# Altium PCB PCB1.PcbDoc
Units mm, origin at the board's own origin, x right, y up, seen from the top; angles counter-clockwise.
Board outline 99 x 59.87 mm, 2 copper layers (Top Layer, Bottom Layer); 24 components, 21 nets, 124 pads, 0 vias.
Unrouted connection lines stored in the file: 1.
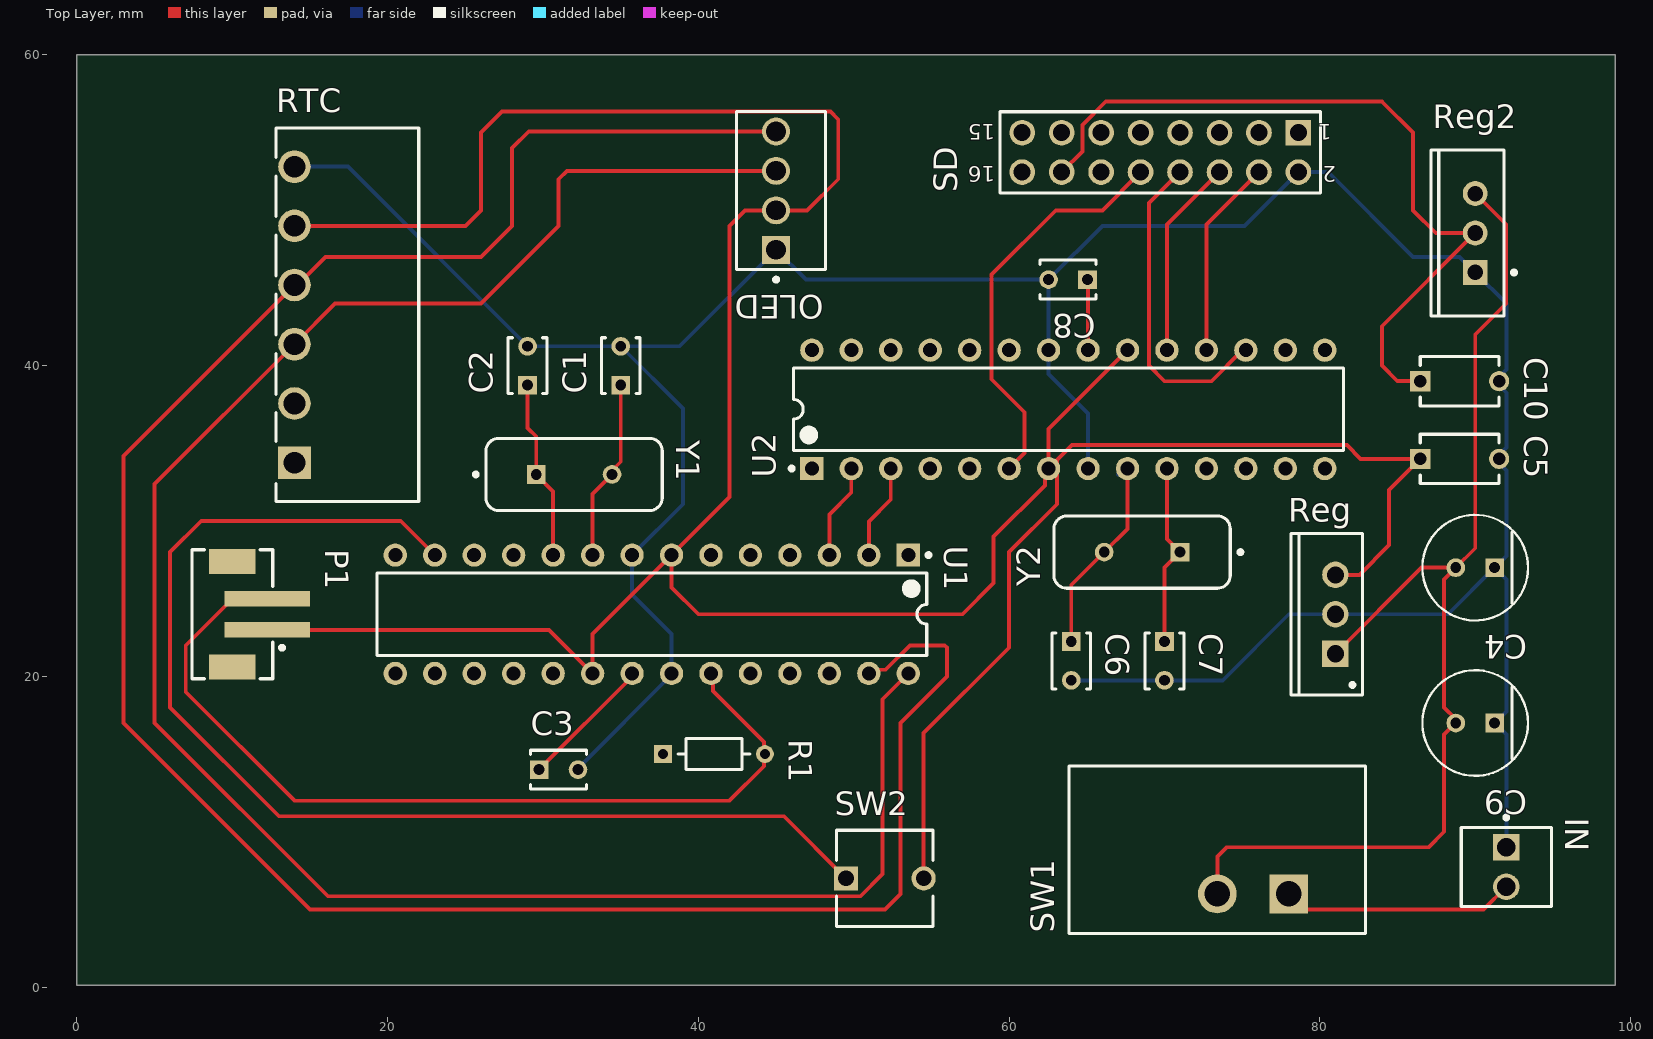
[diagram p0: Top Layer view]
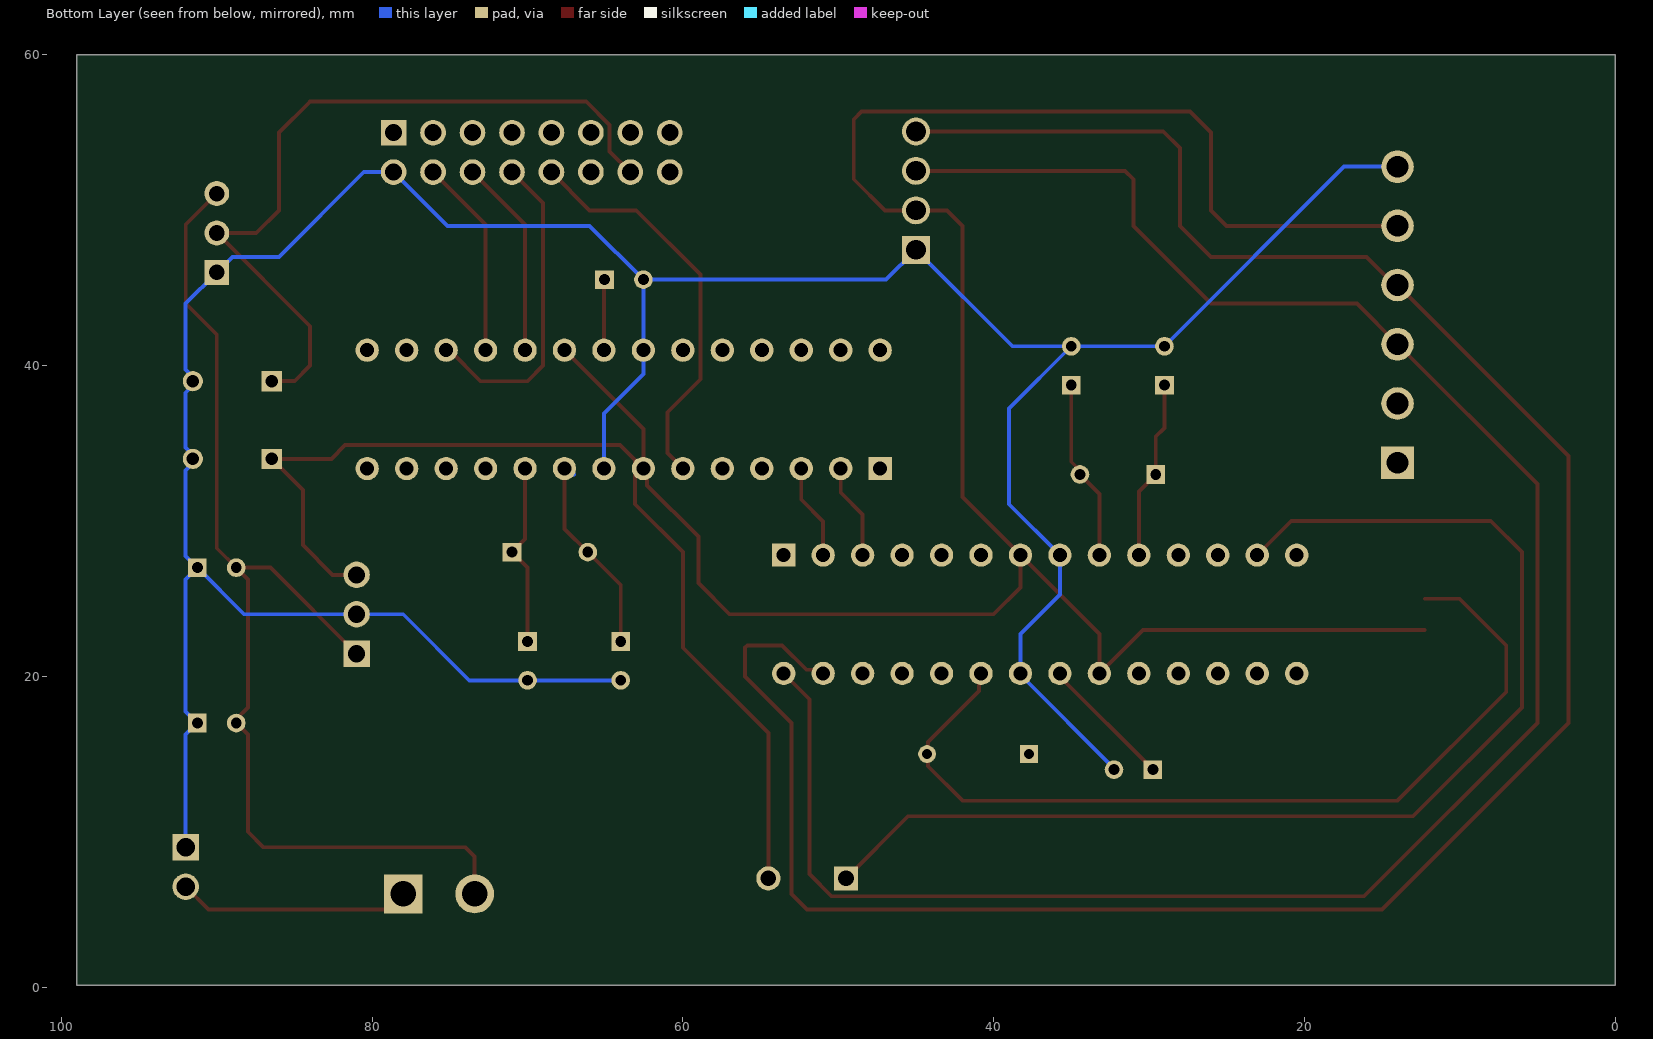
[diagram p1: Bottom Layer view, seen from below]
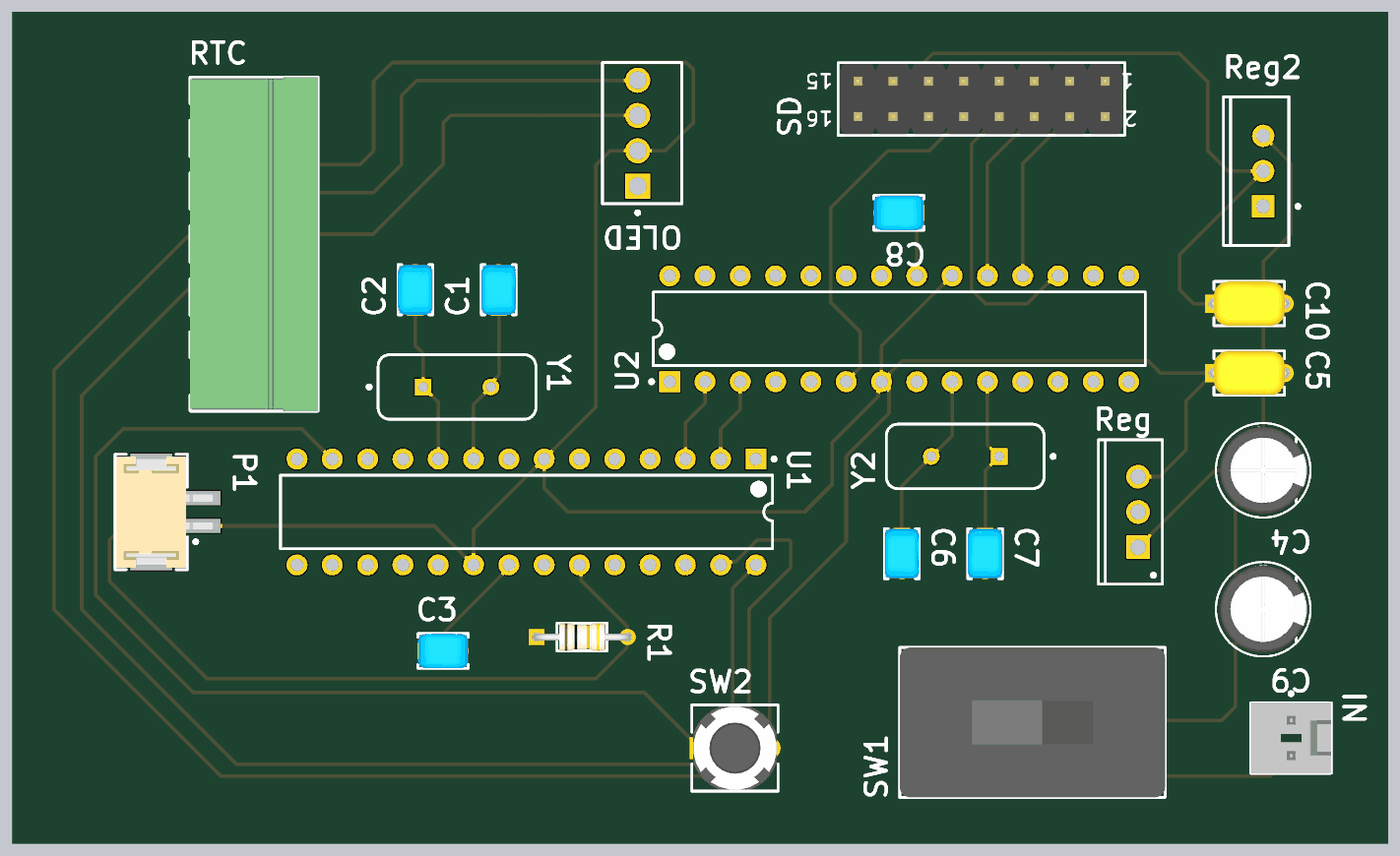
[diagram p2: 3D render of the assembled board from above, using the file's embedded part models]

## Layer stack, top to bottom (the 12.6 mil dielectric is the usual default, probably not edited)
Top Solder: solder mask 0.0102, Solder Resist, Dk 3.5
Top Layer: signal copper 0.0356
Dielectric 1: dielectric 0.32, FR-4, Dk 4.8
Bottom Layer: signal copper 0.0356
Bottom Solder: solder mask 0.0102, Solder Resist, Dk 3.5

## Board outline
0,0.127 99,0.127 99,60 0,60

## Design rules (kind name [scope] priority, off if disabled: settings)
Clearance [All] p1: gap=0.25 ignorepadtopadclearanceinfootprint=FALSE
PolygonConnect [All] p1: connectstyle=Relief reliefconductorwidth=0.254 reliefentries=4 polygonreliefangle="90 Angle" airgapwidth=0.254
RoutingVias [All] p1: holewidth=0.4 width=0.5 viastyle="Through Hole" minholewidth=0.4 minwidth=0.5 maxholewidth=0.8 maxwidth=1
SolderMaskExpansion [All] p1: expansion=0.102 istentingtop=FALSE
Width power [(InNet('3.3V') OR InNet('5V') OR InNet('GND'))] p1: maxlimit=0.3 minlimit=0.2 preferedwidth=0.254
Width [All] p2: maxlimit=0.3 minlimit=0.1 preferedwidth=0.25
30 further rules are at their usual default settings.

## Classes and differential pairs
component class Sheet1: C1 C2 C3 C4 C5 C6 C7 C8 C9 C10 IN OLED P1 R1 Reg Reg2 SD SW1 SW2 U1 Y2

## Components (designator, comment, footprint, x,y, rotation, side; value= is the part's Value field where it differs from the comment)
C1 "22pF" FP-RCE0DB-MFG 35,40 r90 top
C2 "22pF" FP-RCE0DB-MFG 29,40 r90 top
C3 "100nF" FP-RCE0DB-MFG 31,14 r0 top
C4 "4.7uF" FP-RAD-TH-D_6_3_0_5-L_11-MFG 90,27 r180 top
C5 "100nF" FP-C322C104K5R5TA-MFG 89,34 r0 top
C6 "22pF" FP-RCE0DB-MFG 64,21 r270 top
C7 "22pF" FP-RCE0DB-MFG 70,21 r270 top
C8 "100nF" FP-RCE0DB-MFG 63.79,45.54 r180 top
C9 "10uF" FP-RAD-TH-D_6_3_0_5-L_11-MFG 90,17 r180 top
C10 "22uF" FP-C322C104K5R5TA-MFG 89,39 r0 top
IN "9V" MOLX-22-27-2021_V 92,7.73 r270 top
OLED "6" TECO-640456-4 45,51.27 r270 top
P1 "probe" 620302124022 10,24 r270 top
R1 "10k" FP-CF18-MFG 41,15 r0 top value=10kΩ
Reg "5V" TO220 81,24 r90 top
Reg2 "3.3V" NDE0003A 90,48.54 r90 top
RTC "691322310006" 691322310006 17.4,43.285 r90 top
SD "61301621121" 61301621121 69.73,53.73 r180 top
SW1 "on/off" FP-L101011MS02Q-MFG 73.4,8.85 r90 top
SW2 "push button" FP-EVQ11Y04K-MFG 52,7 r0 top
U1 "ATmega328P-PU" 28P3 37,24 r270 top
U2 "ATmega328P-PU" 28P3 63.81,37.19 r90 top
Y1 "16MHz" FOX-FOXSLF160-20 32,33 r0 top
Y2 "16MHz" FOX-FOXSLF160-20 68.56,28 r180 top

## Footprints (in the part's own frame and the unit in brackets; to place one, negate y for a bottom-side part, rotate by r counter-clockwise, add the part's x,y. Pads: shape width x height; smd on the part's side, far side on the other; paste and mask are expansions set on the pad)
28P3 [mm] "28-Pin Plastic Dual In-Line Package (PDIP)"
  rect 1.5x1.5 hole 0.9: 1(-3.81,16.51)
  round 1.5 hole 0.9: 2(-3.81,13.97) 3(-3.81,11.43) 4(-3.81,8.89) 5(-3.81,6.35) 6(-3.81,3.81) 7(-3.81,1.27) 8(-3.81,-1.27) 9(-3.81,-3.81) 10(-3.81,-6.35) 11(-3.81,-8.89) 12(-3.81,-11.43) 13(-3.81,-13.97) 14(-3.81,-16.51) 15(3.81,-16.51) 16(3.81,-13.97) 17(3.81,-11.43) 18(3.81,-8.89) 19(3.81,-6.35) 20(3.81,-3.81) 21(3.81,-1.27) 22(3.81,1.27) 23(3.81,3.81) 24(3.81,6.35) 25(3.81,8.89) 26(3.81,11.43) 27(3.81,13.97) 28(3.81,16.51)
  silkscreen extent -3.93,-17.7 2.65,17.94, body extent -3.6,-17.65 3.6,17.65, height 4.58
61301621121 [mm] "Pin Header, pitch 2.54 mm, THT, Vertical, dual row, 16p"
  rect 1.65x1.65 hole 1.1: 1(-8.89,-1.27)
  round 1.65 hole 1.1: 2(-8.89,1.27) 3(-6.35,-1.27) 4(-6.35,1.27) 5(-3.81,-1.27) 6(-3.81,1.27) 7(-1.27,-1.27) 8(-1.27,1.27) 9(1.27,-1.27) 10(1.27,1.27) 11(3.81,-1.27) 12(3.81,1.27) 13(6.35,-1.27) 14(6.35,1.27) 15(8.89,-1.27) 16(8.89,1.27)
  silkscreen extent -10.31,-2.62 10.31,2.62, body extent -10.16,-2.54 10.16,2.54, height 8.59
620302124022 [mm] "2.00mm SMT Male Vertical Shrouded Header, 2p"
  rect 1x5.5 smd: 1(1,2.25) 2(-1,2.25)
  rect 1.6x3 smd: MP1(-3.4,0) MP2(3.4,0)
  silkscreen extent -4.15,-2.6 4.15,3.32, body extent -4,-2.5 4,4.51, height 6.77
691322310006 [mm] "Horizontal PCB Header, pitch 3.81mm, 06p"
  rect 2.1x2.1 hole 1.4: 1(-9.525,3.4)
  round 2.1 hole 1.4: 2(-5.715,3.4) 3(-1.905,3.4) 4(1.905,3.4) 5(5.715,3.4) 6(9.525,3.4)
  silkscreen extent -12.02,-4.6 12.03,4.6, body extent -12.02,-4.6 12.02,4.6, height 7.25
FOX-FOXSLF160-20 [mm] "THD, 2-Leads, Body 11.35x4.65mm"
  rect 1.2x1.2 hole 0.7: 1(-2.44,0)
  round 1.2 hole 0.7: 2(2.44,0)
  silkscreen extent -6.45,-2.32 5.68,2.32, body extent -5.67,-2.32 5.68,2.33, height 3.6
FP-C322C104K5R5TA-MFG [mm]
  rect 1.3x1.3 hole 0.8 paste-1000 mask+0: 1(-2.54,0)
  round 1.3 hole 0.8 paste-1000 mask+0: 2(2.54,0)
  silkscreen extent -2.54,-1.59 2.54,1.59, body extent -3.29,-1.69 3.29,1.69, height 0.25
FP-CF18-MFG [mm]
  rect 1.15x1.15 hole 0.65 paste-1000 mask+0: 1(-3.28,0)
  round 1.15 hole 0.65 paste-1000 mask+0: 2(3.28,0)
  silkscreen extent -2.3,-1 2.3,1, body extent -3.96,-1.1 3.96,1.1, height 0.25
FP-EVQ11Y04K-MFG [mm]
  rect 1.55x1.55 hole 1 paste-1000 mask+0: A(-2.5,0)
  round 1.55 hole 1 paste-1000 mask+0: B(2.5,0)
  silkscreen extent -3.1,-3.1 3.1,3.1, body extent -3.37,-3.2 3.37,3.2, height 0.25
FP-L101011MS02Q-MFG [mm]
  rect 2.5x2.5 hole 1.65 paste-1000 mask+0: 1(-2.85,-4.6)
  round 2.5 hole 1.65 paste-1000 mask+0: 2(-2.85,0)
  silkscreen extent -5.4,-9.55 5.4,9.55, body extent -5.5,-9.65 5.5,9.65, height 0.25
FP-RAD-TH-D_6_3_0_5-L_11-MFG [mm]
  rect 1.2x1.2 hole 0.7 paste-1000 mask+0: 1(-1.25,0)
  round 1.2 hole 0.7 paste-1000 mask+0: 2(1.25,0)
  silkscreen extent -3.4,-3.4 3.4,3.4, body extent -3.5,-3.5 3.5,3.5, height 0.25
FP-RCE0DB-MFG [mm]
  rect 1.2x1.2 hole 0.7 paste-1000 mask+0: 1(-1.25,0)
  round 1.2 hole 0.7 paste-1000 mask+0: 2(1.25,0)
  silkscreen extent -1.8,-1.25 1.8,1.25, body extent -1.95,-1.35 1.95,1.35, height 0.25
MOLX-22-27-2021_V [mm] "Header, 2-Leads, Body 5.8x5.08mm"
  rect 1.7x1.7 hole 1.19: 1(-1.27,0)
  round 1.7 hole 1.19: 2(1.27,0)
  silkscreen extent -3.31,-2.9 2.54,2.9, body extent -2.54,-2.9 2.54,2.9, height 11.72
NDE0003A [mm] "FM, 3-Leads, Body 10.7x4.7mm, Pitch 2.54mm"
  rect 1.6x1.6 hole 1: 1(-2.54,0)
  round 1.6 hole 1: 2(0,0) 3(2.54,0)
  silkscreen extent -5.35,-2.63 5.35,2.85, body extent -5.4,-1.9 5.4,2.9, height 19.4
TECO-640456-4 [mm] "Through Hole, 4-Leads, Body 10.16x5.72mm, Pitch 2.54mm"
  rect 1.8x1.8 hole 1.27 paste+0: 1(3.81,0)
  round 1.8 hole 1.27 paste+0: 2(1.27,0) 3(-1.27,0) 4(-3.81,0)
  silkscreen extent -5.08,-2.54 5.86,3.18, body extent -5.08,-2.54 5.08,3.18, height 10.03
TO220 [mm] "TO, Thru-Hole, Vertical, Heatsink Mounted; 3 In-Line Leads; Pitch 2.54 mm"
  rect 1.7x1.7 hole 1.1: 1(-2.54,0)
  round 1.7 hole 1.1: 2(0,0) 3(2.54,0)
  silkscreen extent -5.2,-1.75 5.2,2.85, body extent -5.25,-1.8 5.25,2.9, height 19.7

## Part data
C1 C2 C6 C7: library part CMP-06035-047347-1, "Cap Ceramic 22pF 100V C0G ±5% Radial 2.5mm +125°C Ammo Pack", Case/Package=Radial, Dielectric=C0G, Max Operating Temperature=125°C, Min Operating Temperature=-55°C, Package Quantity=2000, Ratings=AEC-Q200, Resistor Type=Ceramic, Tolerance=5%, Voltage=100V
C3 C8: library part CMP-06035-045506-1, "Cap Ceramic 4.7nF 100V X7R ±10% Radial 2.5mm +125°C Ammo Pack", Case/Package=Radial, Dielectric=X7R, Max Operating Temperature=125°C, Min Operating Temperature=-55°C, Package Quantity=2000, Ratings=AEC-Q200, Resistor Type=Ceramic, Tolerance=10%, Voltage Rating=100V
C4: library part CMP-05427-000237-1, "Aluminum Electrolytic Capacitors (Radial Lead Type) 4.7uF ±20% 160V", Case/Package=Radial, Dielectric Material=Aluminium, Max Operating Temperature=105°C, Min Operating Temperature=-25°C, Package Quantity=200, Ripple Current=43mA, Tolerance=20%, Voltage=160V
C5: library part CMP-03020-034661-1, "CAP CER 0.1UF 50V X7R RADIAL", Case/Package=Radial, Dielectric=X7R, Dielectric Material=Ceramic, Max Operating Temperature=125°C, Min Operating Temperature=-55°C, Package Quantity=500, Tolerance=10%, Voltage=50V
C9: library part CMP-05427-000237-1, "Aluminum Electrolytic Capacitors (Radial Lead Type) 4.7uF ±20% 160V", Capacitance=4.7uF, Case/Package=Radial, Dielectric Material=Aluminium, Max Operating Temperature=105°C, Min Operating Temperature=-25°C, Package Quantity=200, Ripple Current=43mA, Tolerance=20%, Voltage=160V
C10: library part CMP-03020-034661-1, "CAP CER 0.1UF 50V X7R RADIAL", Capacitance=100nF, Case/Package=Radial, Dielectric=X7R, Dielectric Material=Ceramic, Max Operating Temperature=125°C, Min Operating Temperature=-55°C, Package Quantity=500, Tolerance=10%, Voltage=50V
IN: library part CMP-2000-05537-1, "Male Header, Pitch 2.54 mm, 1 x 2 Position, Height 11.7 mm, Tail Length 3.56 mm, 0 to 75 degC, RoHS, Bulk", Current - Max=4A, Manufacturer=Molex, Operating temperature=0°Cto+75°C, Package Description="2-Leads Header, Body 5.08 x 5.8 mm, Pitch 2.54 mm", Package Reference=22-27-2021, Package Version="Rev. BC, 02/2012", PartNumber=0022272021, Voltage - Max=250V
OLED: library part CMP-2000-05419-1, "Male Header, Pitch 2.54 mm, 1 x 4 Position, Height 10.03 mm, Tail Length 3.56 mm, RoHS, Bulk", Color=White, Current, Rating="5 /  / A", Flammability Rating=UL94V-0, Manufacturer="TE Connectivity", Temperature, Operating="-55to+105 /  / degC", Voltage, Rating="250 /  / V"
P1: library part CMP-1502-00660-1, "Male Shrouded Header WR-WTB, SMT, Vertical, pitch 2 mm, 1 x 2 position", Contact Resistance=20mOhm, Manufacturer="Wurth Elektronik", Operating temperature=-25to85degC, Package Reference=620302124022, Working Voltage=100VAC
R1: library part CMP-26528-000002-1, "RES 10K OHM 1/8W 5% CF AXIAL", Manufacturer="Stackpole Electronics", Manufacturer Part Number=CF18JT10K0, Package=CF18, Power Rating=0.125W, Resistance=10kΩ, Temperature="-55°C to +155°C", Temperature Coefficient=0-500ppm/°C, Temperature Range High=+155°C, Temperature Range Low=-55°C, Tolerance=5%, Voltage Rating=250V
Reg: library part CMP-0244-00495-1, "Positive Voltage Regulator, 6V, 3-Pin TO-220"
Reg2: library part CMP-0062-02494-3, "800mA Low-Dropout Linear Regulator, 3-pin TO-220, Pb-Free", Manufacturer="Texas Instruments", PackageTopMarking=NSUZXYTTE#*LM1117T*3.3, PowerWise=N
RTC: library part CMP-1502-01890-1, "Serie 322 - 3.81mm Horizontal PCB Header WR-TBL, 6 pin", Manufacturer="Wurth Elektronik", Operating temperature=-40to105degC
SD: library part CMP-1502-01097-1, "THT Vertical Pin Header WR-PHD, Pitch 2.54 mm, Dual Row, 16 pins", Contact Resistance=20mOhm, Manufacturer="Wurth Elektronik", Operating temperature=-40to105degC, Rated Current=3A, Withstanding Voltage=500VAC, Working Voltage=250VAC
SW1: library part CMP-10038-000020-1, "SWITCH SLIDE SPST 4A 125V", Actuator Color=Black, Contact Current Rating=2A, Current rating=4A, Max Operating Temperature=65°C, Max Voltage Rating (AC)=250V, Max Voltage Rating (DC)=125V, Min Operating Temperature=-30°C, Package Quantity=1, Voltage Rating (DC)=28V
SW2: library part CMP-05618-000106-1, "SWITCH TACTILE SPST-NO 0.02A 15V", Actuator Color=Black, Case/Package=Radial, Contact Resistance=50mR, Max Operating Temperature=70°C, Max Voltage Rating (DC)=15V, Min Operating Temperature=-20°C, Operating Force=1.6N, Package Quantity=1
U1 U2: library part CMP-0095-00013-2, "8-bit AVR Microcontroller, 32KB Flash, 1KB EEPROM, 2KB SRAM, 28-pin PDIP, Industrial Grade (-40°C to 85°C)"
Y1 Y2: library part CMP-1749-00003-1, "Resistance Weld Thru-Hole Crystal, 16 MHz, -20 to 70 degC, 2-Pin THD, RoHS, Bulk", Case\Package=Axial, Max Operating Temperature="155 degC", Min Operating Temperature="-55 degC", Package Quantity=200, Power Rating="250 mW", Resistance="221 kohm", Tolerance=1%, Voltage Rating="250 V"

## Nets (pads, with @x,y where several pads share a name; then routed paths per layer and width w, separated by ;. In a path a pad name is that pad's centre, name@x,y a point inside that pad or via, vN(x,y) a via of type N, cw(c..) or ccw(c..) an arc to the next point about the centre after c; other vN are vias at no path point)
3.3V: C10.1 Reg2.2 SD.14 | length 49.8
  Top Layer w0.254: SD.14 64.718,53.798 64.718,55.498 66.22,57 84,57 84.074,56.926 86,55 86,50 87.46,48.54 Reg2.2 84,42.54 84,40 85,39 C10.1
5V: C5.1 OLED.2 P1.1 Reg.3 RTC.5 SW2.B U1.7 U1.20 U2.7 U2.20 | length 217.2
  Top Layer w0.254: P1.1 30.38,23 U1.20 33.19,22.73 U1.7 ; RTC.5 25,49 26,50 26,55 27.357,56.357 48.494,56.357 49,55.851 49,52 47,50 OLED.2 43,50 42,49 42,31.54 U1.7 ; SW2.B 54.5,16.345 60,21.845 60,28 63.08,31.08 63.08,33.38 63.08,33.92 ; U2.20 62.54,35.92 U2.7 ; Reg.3@80.609,26.54 Reg.3 82.54,26.54 84.46,28.46 84.46,32 C5.1 82.618,34 81.735,34.884 64.044,34.884 63.08,33.92 ; U1.7 38.27,25.73 40,24 57,24 59,26 59,29 62.302,32.302 62.302,33.142 U2.7 ; U2.7 63.08,33.92
A0: P1.2 R1.2 U1.23 | length 58
  Top Layer w0.25: P1.2 10,25 7,22 7,19 14,12 42,12 44.218,14.218 44.218,14.938 R1.2 44.218,15.062 44.218,15.782 40.935,19.065 40.935,20.065 U1.23
A4: OLED.4 RTC.4 U1.27 | length 149.1
  Top Layer w0.25: OLED.4 29.08,55.08 28,54 28,49 26,47 16,47 14.19,45.19 RTC.4 3,34.19 3,17 15,5 52,5 53,6 53,17 56,20 56,21.854 55.854,22 53.618,22 52.047,20.429 51.209,20.429 U1.27
A5: OLED.3 RTC.3 U1.28 | length 131.2
  Top Layer w0.25: OLED.3 31.54,52.54 31,52 31,49 26,44 16.62,44 RTC.3 5,32.38 5,17 16.15,5.85 50.43,5.85 51.851,7.27 51.851,18.531 U1.28
CS: SD.10 U2.6 | length 26.1
  Top Layer w0.25: U2.6 61,34.38 61,37 58.875,39.125 58.875,45.875 63,50 66,50 SD.10
D0: U1.3 U2.2 | length 6.2
  Top Layer w0.25: U1.3 48.43,30.43 49.84,31.84 U2.2
D1: U1.2 U2.3 | length 6.2
  Top Layer w0.25: U1.2 50.97,29.97 52.38,31.38 U2.3
D7: SW2.A U1.13 | length 76.8
  Top Layer w0.25: U1.13 20.84,30 8,30 6,28 6,18 13,11 45.5,11 SW2.A
GND: C1.2 C2.2 C3.2 C4.1 C5.2 C6.2 C7.2 C8.2 C9.1 C10.2 IN.1 OLED.1 R1.1 Reg2.1 Reg.2 RTC.6 SD.2 U1.8 U1.22 U2.8 U2.22 | length 206.8
  Bottom Layer w0.254: RTC.6 17.44,52.81 C2.2 C1.2 ; C3.2 32.25,14.085 38.27,20.105 U1.22 38.27,22.73 35.73,25.27 U1.8 39,31.08 39,37.25 C1.2 ; C6.2 C7.2 73.75,19.75 78,24 Reg.2 88.25,24 C4.1 ; U2.8 65.08,36.92 62.54,39.46 U2.22 C8.2 ; IN.1 92,16.25 C9.1 92,17.75 92,26.25 C4.1 ; C1.2 38.79,41.25 OLED.1 46.92,45.54 C8.2 ; C8.2 66,49 75.16,49 SD.2 80.54,52.46 86,47 89,47 Reg2.1 92,44 92,39.743 91.54,39.283 C10.2 91.54,38.717 92,38.257 92,34.743 91.54,34.283 C5.2 91.54,33.717 92,33.257 92,27.75 C4.1
MISO: SD.4 U2.18 | length 12.9
  Top Layer w0.25: U2.18 72.7,49.08 SD.4
MOSI: SD.8 U2.17 | length 20.8
  Top Layer w0.25: SD.8 69,50.46 69,40 70,39 73.026,39 75.026,41 U2.17
NetC1_1: C1.1 U1.9 Y1.2 | length 11.9
  Top Layer w0.25: U1.9@33.315,27.935 U1.9 33.19,31.75 Y1.2 34.44,33.257 35,33.817 C1.1
NetC2_1: C2.1 U1.10 Y1.1 | length 11.6
  Top Layer w0.25: C2.1 29,36 29.56,35.44 Y1.1 30.65,31.91 U1.10
NetC3_1: C3.1 U1.21 | length 8.7
  Top Layer w0.25: C3.1 35.73,19.98 U1.21
NetC4_2: C4.2 C9.2 Reg2.3 Reg.1 SW1.2 | length 71.9
  Top Layer w0.25: SW1.2 73.4,8.4 74,9 87,9 88,10 88,16.25 C9.2 88.75,17.25 88,18 88,26.25 C4.2 ; Reg.1 86.54,27 C4.2 ; Reg2.3 92,49.08 92,44 90,42 90,28.25 C4.2
NetC6_1: C6.1 U2.9 Y2.2 | length 13.7
  Top Layer w0.25: C6.1 64,25.88 Y2.2 67.62,29.5 U2.9 ; Y2.2@65.68,27.743 Y2.2@65.68,28
  Bottom Layer w0.25: U2.9@67,33 67.38,33.38 U2.9
NetC7_1: C7.1 U2.10 Y2.1 | length 11.9
  Top Layer w0.25: C7.1 70,27 Y2.1 70.16,28.84 U2.10
NetC8_1: C8.1 U2.21 | length 4.6
  Top Layer w0.25: C8.1 65.08,45.5 U2.21
NetIN_2: IN.2 SW1.1 | length 15
  Top Layer w0.25: SW1.1 79,5 90.54,5 IN.2
SCK: SD.6 U2.19 | length 12.9
  Top Layer w0.25: U2.19 70.16,49.08 SD.6
pads on no net: P1.MP1 P1.MP2 RTC.1 RTC.2 SD.1 SD.3 SD.5 SD.7 SD.9 SD.11 SD.12 SD.13 SD.15 SD.16 U1.1 U1.4 U1.5 U1.6 U1.11 U1.12 U1.14 U1.15 U1.16 U1.17 U1.18 U1.19 U1.24 U1.25 U1.26 U2.1 U2.4 U2.5 U2.11 U2.12 U2.13 U2.14 U2.15 U2.16 U2.23 U2.24 U2.25 U2.26 U2.27 U2.28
